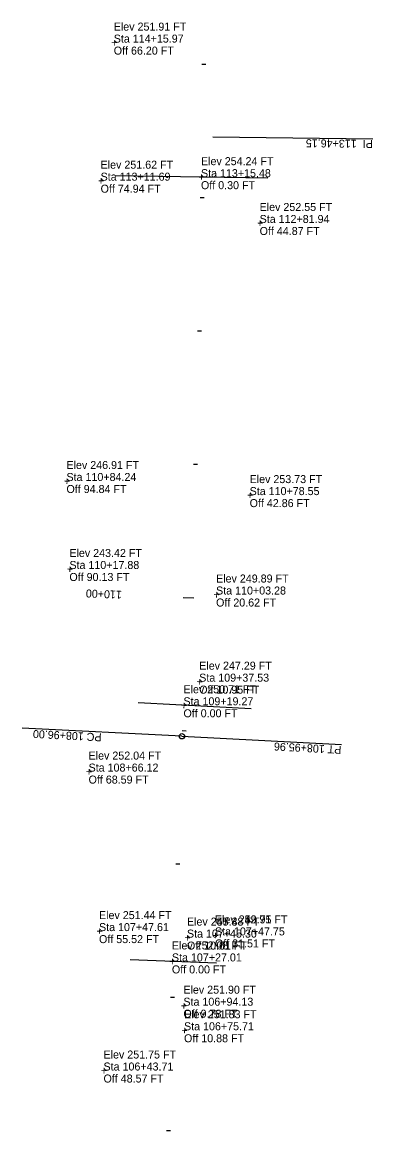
# Model space of a CAD drawing. Extents: x 1930770 to 1938778, y 596900 to 600561.
# Drawn here: x 1930793 to 1931056, y 597731 to 598562 of the extents above; entities that cross this region are included whole.
import ezdxf

# ---------------------------------------------------------------- set-up
doc = ezdxf.new("R2010")
doc.units = 0
for name, color, linetype in [('22', 7, 'Continuous'), ('E_Tract Residual', 7, 'Continuous'), ('S_MISC_STRUCTURES_ANNOT', 7, 'Continuous'), ('S_STORM_SEWER_ANNOT', 7, 'Continuous')]:
    doc.layers.add(name, color=color, linetype=linetype)

msp = doc.modelspace()

# ---------------------------------------------------------------- linework, layer by layer
at = {"layer": 'E_Tract Residual'}
for points in [[(1930930.91, 598530.71), (1930927.91, 598530.74)], [(1930936.21, 598476.55), (1931056.2, 598475.06)], [(1930929.71, 598430.7), (1930926.71, 598430.74)], [(1930927.63, 598330.69), (1930924.63, 598330.77)], [(1930924.67, 598230.71), (1930921.67, 598230.81)], [(1930913.85, 598131.05), (1930921.85, 598130.71)], [(1930912.95, 598027), (1930793.11, 598033.2)], [(1930916.15, 598030.84), (1930913.15, 598030.99)], [(1930912.94, 598026.96), (1931032.78, 598020.76)], [(1930911.38, 597930.98), (1930908.39, 597931.11)], [(1930907.49, 597831.08), (1930904.49, 597831.18)], [(1930904.47, 597731.15), (1930901.47, 597731.23)]]:
    msp.add_lwpolyline(points, dxfattribs=at)
for centre in [(1930912.94, 598026.96), (1930912.95, 598027)]:
    msp.add_circle(centre, 2, dxfattribs=at)
at = {"layer": 'S_MISC_STRUCTURES_ANNOT'}
for p, q in [((1930977.45, 598445.46), (1930862.66, 598447.19)), ((1930964.97, 598047.5), (1930880.15, 598052.06)), ((1930938.95, 597856.94), (1930874.04, 597859.34))]:
    msp.add_line(p, q, dxfattribs=at)

# ---------------------------------------------------------------- texts
at = {"layer": '22'}
for s, p in [('Elev 251.91 FT ', (1930861.83, 598556.12)), ('Sta 114+15.97 ', (1930861.83, 598547.12)), ('Off 66.20 FT  ', (1930861.83, 598538.12)), ('Elev 251.62 FT ', (1930851.96, 598452.59)), ('Sta 113+11.69 ', (1930851.96, 598443.59)), ('Off 74.94 FT  ', (1930851.96, 598434.59)), ('Elev 252.55 FT ', (1930971.26, 598420.87)), ('Sta 112+81.94 ', (1930971.26, 598411.87)), ('Off 44.87 FT  ', (1930971.26, 598402.87)), ('Elev 246.91 FT ', (1930826.35, 598227.4)), ('Sta 110+84.24 ', (1930826.35, 598218.4)), ('Elev 253.73 FT ', (1930963.76, 598216.83)), ('Off 94.84 FT  ', (1930826.35, 598209.4)), ('Sta 110+78.55 ', (1930963.76, 598207.83)), ('Off 42.86 FT  ', (1930963.76, 598198.83)), ('Elev 243.42 FT ', (1930828.55, 598161.44)), ('Sta 110+17.88 ', (1930828.55, 598152.44)), ('Off 90.13 FT  ', (1930828.55, 598143.44)), ('Elev 249.89 FT ', (1930938.59, 598142.29)), ('Sta 110+03.28 ', (1930938.59, 598133.29)), ('Off 20.62 FT  ', (1930938.59, 598124.29)), ('Elev 247.29 FT ', (1930925.96, 598076.95)), ('Sta 109+37.53 ', (1930925.96, 598067.95)), ('Off 10.95 FT  ', (1930925.96, 598058.95)), ('Elev 252.04 FT ', (1930842.94, 598009.52)), ('Sta 108+66.12 ', (1930842.94, 598000.52)), ('Off 68.59 FT  ', (1930842.94, 597991.52)), ('Elev 251.44 FT ', (1930850.76, 597889.91)), ('Elev 255.38 FT ', (1930916.75, 597885.04)), ('Elev 247.43 FT ', (1930916.75, 597885.04)), ('Elev 252.95 FT ', (1930937.73, 597886.68)), ('Elev 249.71 FT ', (1930937.73, 597886.68)), ('Sta 107+47.61 ', (1930850.76, 597880.91)), ('Sta 107+45.30 ', (1930916.75, 597876.04)), ('Sta 107+45.30 ', (1930916.75, 597876.04)), ('Sta 107+47.75 ', (1930937.73, 597877.68)), ('Sta 107+47.75 ', (1930937.73, 597877.68)), ('Off 55.52 FT  ', (1930850.76, 597871.91)), ('Off 10.61 FT  ', (1930916.75, 597867.04)), ('Off 10.61 FT  ', (1930916.75, 597867.04)), ('Off 31.51 FT  ', (1930937.73, 597868.68)), ('Off 31.51 FT  ', (1930937.73, 597868.68)), ('Elev 251.90 FT ', (1930914.07, 597833.98)), ('Sta 106+94.13 ', (1930914.07, 597824.98)), ('Off 9.78 FT  ', (1930914.07, 597815.98)), ('Elev 251.83 FT ', (1930914.55, 597815.55)), ('Sta 106+75.71 ', (1930914.55, 597806.55)), ('Off 10.88 FT  ', (1930914.55, 597797.55)), ('Elev 251.75 FT ', (1930854.14, 597785.37)), ('Sta 106+43.71 ', (1930854.14, 597776.37)), ('Off 48.57 FT  ', (1930854.14, 597767.37))]:
    msp.add_text(s, height=6, dxfattribs=at).set_placement(p)
for rotation, p in [(359.63815, (1930859.85, 598544.14)), (359.11674, (1930849.95, 598440.62)), (358.96798, (1930969.24, 598408.91)), (357.9795, (1930824.28, 598215.47)), (357.95102, (1930961.7, 598204.91)), (357.64767, (1930826.47, 598149.52)), (357.5747, (1930936.51, 598130.37)), (357.24594, (1930923.85, 598065.05)), (357.18735, (1930840.83, 597997.62)), (357.77989, (1930848.68, 597877.99)), (357.79145, (1930914.68, 597873.12)), (357.79145, (1930914.68, 597873.12)), (357.7792, (1930935.66, 597874.76)), (357.7792, (1930935.66, 597874.76)), (358.04734, (1930912, 597822.05)), (358.1394, (1930912.49, 597803.62)), (358.29939, (1930852.09, 597773.43))]:
    msp.add_text('+', height=6, rotation=rotation, dxfattribs=at).set_placement(p)
at = {"layer": 'E_Tract Residual'}
for s, rotation, p in [('PI  113+46.15', 179.28771, (1931056.18, 598474.06)), ('110+00', 177.55811, (1930868.02, 598136.01)), ('PC 108+96.00', 177.03813, (1930852.83, 598029.11)), ('PT 108+95.96', 177.03813, (1931032.73, 598019.76))]:
    msp.add_text(s, height=6, rotation=rotation, dxfattribs=at).set_placement(p)
at = {"layer": 'S_STORM_SEWER_ANNOT'}
for s, p in [('Elev 254.24 FT ', (1930927.25, 598455.22)), ('Sta 113+15.48 ', (1930927.25, 598446.22)), ('Off 0.30 FT  ', (1930927.25, 598437.22)), ('Elev 250.71 FT ', (1930914.13, 598059.24)), ('Sta 109+19.27 ', (1930914.13, 598050.24)), ('Off 0.00 FT  ', (1930914.13, 598041.24)), ('Elev 252.08 FT ', (1930905.46, 597867.18)), ('Sta 107+27.01 ', (1930905.46, 597858.18)), ('Off 0.00 FT  ', (1930905.46, 597849.18))]:
    msp.add_text(s, height=6, dxfattribs=at).set_placement(p)
for rotation, p in [(359.1357, (1930925.25, 598443.25)), (357.15464, (1930912.02, 598047.34)), (357.8829, (1930903.39, 597855.25))]:
    msp.add_text('+', height=6, rotation=rotation, dxfattribs=at).set_placement(p)

doc.saveas('drawing.dxf')
